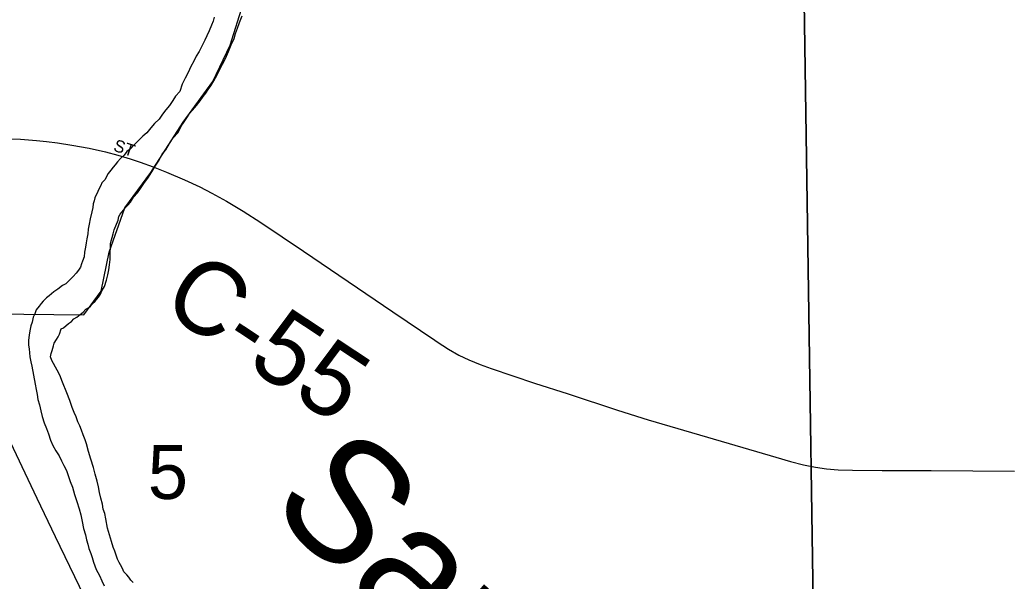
# Model space of a CAD drawing. Extents: x -17 to 88, y -5 to 22.
# Drawn here: x 4.109 to 4.88, y 19.57 to 20.006 of the extents above; entities that cross this region are included whole.
import ezdxf

# ---------------------------------------------------------------- set-up
doc = ezdxf.new("R2010")
doc.units = 0
for name, color, linetype in [('GM_X_City_Street', 7, 'Continuous'), ('GM_X_City_Street_Text', 7, 'Continuous'), ('GM_X_Corporation', 7, 'Continuous'), ('GM_X_County_Road', 7, 'Continuous'), ('GM_X_County_Road_Text', 7, 'Continuous'), ('GM_X_Major_River', 7, 'Continuous'), ('GM_X_Major_River_Text', 7, 'Continuous'), ('GM_X_Section', 7, 'Continuous'), ('GM_X_Section_Text', 7, 'Continuous'), ('GM_X_State_Route', 7, 'Continuous')]:
    doc.layers.add(name, color=color, linetype=linetype)

msp = doc.modelspace()

# ---------------------------------------------------------------- linework, layer by layer
at = {"layer": 'GM_X_City_Street'}
msp.add_lwpolyline([(3.98897, 19.91342), (4.03061, 19.91388), (4.05418, 19.91395), (4.07341, 19.91405), (4.08382, 19.91386), (4.09455, 19.91365), (4.10193, 19.91332), (4.10946, 19.91298), (4.12187, 19.91195), (4.1295, 19.91128), (4.13795, 19.91015), (4.14905, 19.90855), (4.16251, 19.90601), (4.17527, 19.90316), (4.18489, 19.90063), (4.19439, 19.89779), (4.20209, 19.89536), (4.21223, 19.89158)], dxfattribs=at)
at = {"layer": 'GM_X_Corporation'}
msp.add_lwpolyline([(4.01874, 19.77849), (4.15841, 19.77688), (4.17184, 19.79505), (4.17814, 19.82536), (4.19016, 19.8598), (4.21048, 19.88734), (4.23545, 19.92623), (4.25846, 19.95792), (4.27195, 19.9859), (4.28206, 20.01807), (4.28192, 20.0507), (4.26738, 20.088), (4.25199, 20.11278), (4.23047, 20.13002), (4.24063, 20.16902), (4.23331, 20.20588), (4.21822, 20.22042), (4.1868, 20.2328), (4.13217, 20.23929), (4.11966, 20.24242), (4.08749, 20.25708)], dxfattribs=at)
at = {"layer": 'GM_X_County_Road'}
for points in [[(4.21223, 19.89158), (4.22266, 19.88745), (4.2364, 19.88156), (4.24827, 19.87604), (4.25772, 19.87125), (4.26916, 19.86491), (4.28199, 19.85723), (4.29563, 19.84851), (4.32865, 19.8263), (4.39811, 19.77924), (4.43068, 19.75708)], [(4.43068, 19.75708), (4.43245, 19.75588), (4.44127, 19.7502), (4.4493, 19.7456), (4.45704, 19.74181), (4.4656, 19.7383), (4.47433, 19.73515), (4.5079, 19.7239), (4.53393, 19.71553), (4.57225, 19.70276), (4.59598, 19.69541), (4.66932, 19.67382), (4.69501, 19.66642), (4.70631, 19.66307), (4.71651, 19.66052), (4.7256, 19.65869), (4.73414, 19.65745), (4.74337, 19.65667), (4.7545, 19.65627), (4.77749, 19.65614), (4.81541, 19.65604), (4.88003, 19.65562)]]:
    msp.add_lwpolyline(points, dxfattribs=at)
at = {"layer": 'GM_X_Major_River'}
for points in [[(4.25948, 20.00763), (4.2587, 20.0046), (4.25754, 20.00158), (4.25561, 19.99704), (4.25368, 19.99326), (4.25214, 19.98986), (4.25021, 19.9857), (4.2479, 19.98117), (4.24559, 19.97739), (4.24367, 19.97361), (4.24136, 19.96945), (4.23943, 19.96491), (4.23712, 19.96038), (4.2348, 19.95584), (4.23287, 19.95017), (4.22942, 19.9464), (4.2275, 19.943), (4.22481, 19.93922), (4.22213, 19.93583), (4.21945, 19.93243), (4.21676, 19.92866), (4.21332, 19.92527), (4.21026, 19.92188), (4.20719, 19.91811), (4.20413, 19.91548), (4.20145, 19.91246)], [(4.21115, 19.88773), (4.21384, 19.89226), (4.21691, 19.89679), (4.21922, 19.90132), (4.2219, 19.90472), (4.22498, 19.90963), (4.22767, 19.91416), (4.23149, 19.9183), (4.23381, 19.92322), (4.23611, 19.92662), (4.2388, 19.93039), (4.24033, 19.93303), (4.24263, 19.93567), (4.24569, 19.93906), (4.24876, 19.94283), (4.25106, 19.94623), (4.25298, 19.94887), (4.2549, 19.95152), (4.25682, 19.95453), (4.25912, 19.95831), (4.26143, 19.96247), (4.26374, 19.96663), (4.26605, 19.97116), (4.26836, 19.9757), (4.27068, 19.98099), (4.27262, 19.98629), (4.27493, 19.9912), (4.2761, 19.99499), (4.27765, 19.99915), (4.2792, 20.00369), (4.28113, 20.00861)], [(4.20145, 19.91246), (4.19725, 19.90832), (4.19457, 19.90569), (4.1919, 19.90343), (4.1896, 19.90079), (4.18692, 19.89815), (4.18463, 19.89552), (4.18271, 19.89325), (4.18118, 19.89137), (4.17926, 19.88911), (4.17734, 19.88647), (4.17465, 19.88155), (4.17236, 19.87929), (4.17158, 19.87702), (4.17042, 19.87476), (4.16927, 19.87249), (4.16695, 19.86757), (4.16656, 19.8653), (4.16578, 19.86303), (4.16538, 19.86), (4.1646, 19.85659), (4.16342, 19.85128), (4.16263, 19.84712), (4.16184, 19.84333), (4.16143, 19.83954), (4.16065, 19.83575), (4.16024, 19.83272), (4.15984, 19.82931), (4.15905, 19.82552), (4.15865, 19.82173), (4.15748, 19.81832), (4.15671, 19.81643), (4.15593, 19.81378), (4.15439, 19.81151), (4.15248, 19.80925), (4.15018, 19.80661), (4.1475, 19.80398), (4.14445, 19.80097), (4.14178, 19.79947), (4.13834, 19.79684), (4.13529, 19.79459), (4.13147, 19.79158), (4.12956, 19.79008), (4.12688, 19.78744), (4.12535, 19.78556), (4.12382, 19.78367), (4.12152, 19.78065), (4.12035, 19.77763), (4.1192, 19.77498), (4.11841, 19.77119), (4.11725, 19.76817), (4.11646, 19.76438), (4.11606, 19.76096), (4.11565, 19.75717), (4.11562, 19.75338), (4.11598, 19.75034), (4.11634, 19.7473), (4.11669, 19.74426), (4.11743, 19.74047), (4.11816, 19.73705), (4.12071, 19.72299), (4.12145, 19.71881), (4.12218, 19.71501), (4.12291, 19.71121), (4.12402, 19.70703), (4.12512, 19.70246), (4.12623, 19.6979), (4.12771, 19.69296), (4.12958, 19.68877), (4.13107, 19.68459), (4.13255, 19.67964), (4.13442, 19.67545), (4.13667, 19.67126), (4.1393, 19.66745), (4.14117, 19.66364), (4.14304, 19.65983), (4.14491, 19.65602), (4.1464, 19.65222), (4.14789, 19.64765), (4.14975, 19.64309), (4.15123, 19.63738), (4.15309, 19.63206), (4.15494, 19.62635), (4.15605, 19.62179), (4.15715, 19.61647), (4.15825, 19.61115), (4.15973, 19.60621), (4.16046, 19.60241), (4.16158, 19.59899), (4.16231, 19.59556), (4.1638, 19.59176), (4.16492, 19.58871), (4.16603, 19.58491), (4.16789, 19.5792), (4.17051, 19.57463), (4.17238, 19.57045), (4.17425, 19.56663)], [(4.19667, 19.56912), (4.19479, 19.57103), (4.19328, 19.57332), (4.19178, 19.57523), (4.18952, 19.57752), (4.1884, 19.58019), (4.1869, 19.58286), (4.18578, 19.58476), (4.18465, 19.58743), (4.18354, 19.59047), (4.18242, 19.59351), (4.1813, 19.59656), (4.17982, 19.60112), (4.17834, 19.60606), (4.17686, 19.61139), (4.17539, 19.61861), (4.17466, 19.62279), (4.17355, 19.62621), (4.17282, 19.63001), (4.17171, 19.63457), (4.1706, 19.63913), (4.16987, 19.64331), (4.16877, 19.64787), (4.16729, 19.6532), (4.16581, 19.65852), (4.16396, 19.66499), (4.1621, 19.67069), (4.16063, 19.67677), (4.15951, 19.67982), (4.15802, 19.68362), (4.15653, 19.68743), (4.15541, 19.69085), (4.15392, 19.6939), (4.15242, 19.6977), (4.15093, 19.70113), (4.14944, 19.70493), (4.14758, 19.71026), (4.14535, 19.71635), (4.14199, 19.72472), (4.13975, 19.73005), (4.13788, 19.73386), (4.13376, 19.74148), (4.13264, 19.74414), (4.13304, 19.7468), (4.13382, 19.74907), (4.13498, 19.75285), (4.13538, 19.75475), (4.1373, 19.75777), (4.13845, 19.75966), (4.1396, 19.76192), (4.14077, 19.76609), (4.14268, 19.76683), (4.1465, 19.77022), (4.14879, 19.77172), (4.1507, 19.7736), (4.15299, 19.7751), (4.15566, 19.77698), (4.15795, 19.77886), (4.15987, 19.78112), (4.1633, 19.78299), (4.16522, 19.78563), (4.16713, 19.78751), (4.16981, 19.79053), (4.17135, 19.79279), (4.1725, 19.79544), (4.17442, 19.79884), (4.17598, 19.80376), (4.17715, 19.80793), (4.17794, 19.81171), (4.17835, 19.81551), (4.17876, 19.81968), (4.17878, 19.82271), (4.1788, 19.82575), (4.1792, 19.8284), (4.17922, 19.83181), (4.17962, 19.83409), (4.1804, 19.83674), (4.18118, 19.83977), (4.18196, 19.8428), (4.18505, 19.85036), (4.18545, 19.85302), (4.1866, 19.8549), (4.18928, 19.85792), (4.19082, 19.86018), (4.19273, 19.86206), (4.19465, 19.86433), (4.19695, 19.8681), (4.20002, 19.8715), (4.20232, 19.87489), (4.205, 19.87867), (4.20807, 19.88282), (4.21115, 19.88773)]]:
    msp.add_lwpolyline(points, dxfattribs=at)
at = {"layer": 'GM_X_Section'}
for points in [[(4.7146, 20.17531), (4.72971, 19.15674), (3.73257, 19.16304), (3.7219, 20.17019)], [(5.72232, 20.1762), (5.72057, 19.1483), (4.72971, 19.15674), (4.7146, 20.17531)]]:
    msp.add_lwpolyline(points, close=True, dxfattribs=at)
at = {"layer": 'GM_X_State_Route'}
msp.add_lwpolyline([(4.23947, 19.39009), (4.22253, 19.42539), (4.17101, 19.53237), (4.155, 19.56605), (4.13638, 19.6047), (4.12218, 19.63442), (4.09684, 19.68777), (4.08217, 19.71796), (4.05373, 19.77808)], dxfattribs=at)

# ---------------------------------------------------------------- texts
at = {"layer": 'GM_X_City_Street_Text'}
msp.add_text('ST', height=0.00947, rotation=341.55631, dxfattribs=at).set_placement((4.18072, 19.90427))
at = {"layer": 'GM_X_County_Road_Text'}
msp.add_text('C-55', height=0.056818, rotation=326.57034, dxfattribs=at).set_placement((4.21669, 19.78157))
at = {"layer": 'GM_X_Major_River_Text'}
msp.add_text('Sandusky', height=0.094716, rotation=316.57826, dxfattribs=at).set_placement((4.30008, 19.62736))
at = {"layer": 'GM_X_Section_Text'}
msp.add_text('5', height=0.04186, rotation=0.00001, dxfattribs=at).set_placement((4.20807, 19.63399))

doc.saveas('drawing.dxf')
